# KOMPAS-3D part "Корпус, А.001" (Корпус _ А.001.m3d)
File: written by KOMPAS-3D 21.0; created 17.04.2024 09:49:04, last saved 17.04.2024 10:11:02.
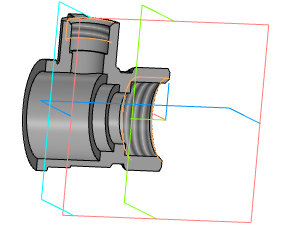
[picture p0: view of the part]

Document properties: Автор: Admin; Полное имя файла: C:\Users\wsr\Desktop\Чертежи\Детали\Корпус _ А.001.m3d

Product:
- Part/product: Корпус  | designation А.001
    Масса: 0.057381
  - Body: Тело 1
      Масса: 0.057646

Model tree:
1. Эскиз:1
2. Элемент выдавливания:1
     Расстояние 1 = 10
3. Эскиз:2  (with: Элемент выдавливания:1)
4. Элемент выдавливания:2
     Расстояние 1 = 3
5. Эскиз:3  (with: Элемент выдавливания:2)
6. Элемент выдавливания:3
     Расстояние 1 = 11
7. Эскиз:4  (with: Элемент выдавливания:3)
8. Элемент выдавливания:4
     Расстояние 1 = 6
9. Эскиз:5  (with: Элемент выдавливания:4)
10. Элемент выдавливания:5
     Расстояние 1 = 3
11. Эскиз:6  (with: Элемент выдавливания:5)
12. Элемент выдавливания:6
     Расстояние 2 = 16.5
13. Эскиз:7  (with: Элемент выдавливания:6)
14. Элемент выдавливания:7
     Расстояние 2 = 3.5
15. Эскиз:8  (with: Элемент выдавливания:7)
16. Элемент выдавливания:8
     Расстояние 2 = 80
17. Эскиз:9  (with: Элемент выдавливания:1, Элемент выдавливания:8)
18. Элемент выдавливания:9
     Расстояние 2 = 10
19. Условное изображение резьбы:1  (with: Элемент выдавливания:9)  (labels: cil2_ex_ISO 228)
     Длина резьбы = 8; Шаг резьбы = 1.814; Номинальный диаметр резьбы = 20.955
20. Подгонка:1  (with: Элемент выдавливания:9)
21. Эскиз:10
22. Элемент выдавливания:10
     Расстояние 1 = 24
23. Удалить грани:1  (with: Элемент выдавливания:10)
24. Эскиз:11  (with: Элемент выдавливания:10)
25. Элемент выдавливания:11
     Расстояние 2 = 8
26. Эскиз:12  (with: Элемент выдавливания:11)
27. Элемент выдавливания:12
     Расстояние 2 = 10
28. Условное изображение резьбы:2  (with: Элемент выдавливания:11)  (labels: M12; cil0_24705-2004 coarse)
     Длина резьбы = 5; Шаг резьбы = 1.75; Номинальный диаметр резьбы = 12
29. Подгонка:2  (with: Элемент выдавливания:11)
30. Фаска:1  (with: Элемент выдавливания:11)
     Угол = 45; Длина 1 = 1; Длина 2 = 1
31. Смещенная плоскость:1
     Расстояние = 22
32. Эскиз:13  (with: Элемент выдавливания:10)
33. Элемент выдавливания:13
     Расстояние 1 = 4
34. Эскиз:14  (with: Элемент выдавливания:1, Элемент выдавливания:3)
35. Элемент вращения:1  (with: Элемент выдавливания:3)
     Угол 1 = 360
36. Удалить грани:2  (with: Элемент вращения:1)
37. Удалить грани:3  (with: Элемент вращения:1)
38. Элемент выдавливания:14  (with: Элемент вращения:1)
     Расстояние 1 = 1
39. Элемент выдавливания:15  (with: Элемент вращения:1)
     Расстояние 1 = 1
40. Фаска:2  (with: Элемент выдавливания:4)
     Угол = 15; Длина 1 = 0.5; Длина 2 = 0.133975
41. Фаска:3  (with: Элемент выдавливания:5)
     Угол = 15; Длина 1 = 1; Длина 2 = 0.267949
42. Скругление:1  (with: Элемент выдавливания:10)
     Радиус = 1
43. Фаска:4  (with: Элемент выдавливания:9)
     Угол = 45; Длина 1 = 1; Длина 2 = 1

Expressions: 23/2; G 1/2
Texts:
  Точка начала. Х
  Точка начала. Y
  Точка начала. Z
